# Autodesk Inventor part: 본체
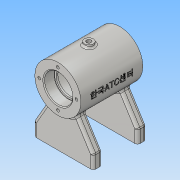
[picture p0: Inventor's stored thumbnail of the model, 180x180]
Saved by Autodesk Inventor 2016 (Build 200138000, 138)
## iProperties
Created: 2018-05
Part Number: 본체
Material: 알루미늄 6061
Document SubType Name: Modeling
Designer: Administrator
Density: 2.7 g/cm^3
Appearance: 알루미늄 - 평지
Mass: 310.015 g
Surface Area: 370.194 cm^2
Volume: 114.821 cm^3
Author: Administrator
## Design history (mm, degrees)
node "작업 평면1"
sketch "스케치1"
  geometry: L1 (32.371, 0)-(-37.629, 0) reference; L2 (32.371, 0)-(-35, 0) reference; L3 (-35, 0)-(-35, 15); L4 (-35, 15)-(32.371, 15); L5 (32.371, 15)-(32.371, 0); L6 (32.371, 15)-(3.504, 65); L7 (3.504, 65)-(-3.504, 65); L8 (-3.504, 65)-(-35, 15); L9 (0, 0)-(0, 88.313) reference; 1 further point
  constraints: 18 end point, 5 horizontal, 2 parallel, 2 perpendicular, 1 midpoint, 1 point on line, 1 vertical, 1 other
  dimensions: "d1" = 70 distance of L1.start L1.end; "d2" = 15 distance of L2.end L3.end; "d3" = 30 deg angle of L5 L6; "d5" = 65 distance between parallel lines of L7 L1
extrude "돌출1" new body sketch "스케치1" distance "d6" = 10; taper "d7" = 0 deg
sketch "스케치2"
  geometry: L1 (0, 0)-(0, 93.301); L2 (-35, 0)-(32.371, 0) reference; C1 r 26 at (0, 65)
  constraints: 2 end point, 1 centre point, 1 point on line, 1 vertical
  dimensions: "d8" = 52 diameter of C1; "d9" = 65 distance from line of L2 C1.centre
extrude "돌출2" join sketch "스케치2" stored distance "d10" = 70; taper "d11" = 0 deg
sketch "스케치3"
  geometry: L1 (20, 44.154)-(30, 44.154) reference; L2 (20, 44.724)-(20, 44.154) reference; L3 (30, 44.724)-(20, 44.724) reference; L4 (30, 44.154)-(30, 44.724) reference; L5 (-30, 44.154)-(-20, 44.154) reference; L6 (-30, 44.724)-(-30, 44.154) reference; L7 (-20, 44.724)-(-30, 44.724) reference; L8 (-20, 44.154)-(-20, 44.724) reference; L9 (-35, 91)-(-35, 39) reference; L10 (35, 39)-(35, 91) reference; L11 (-30, 15)-(-30, 44.154) reference; L12 (-30, 44.154)-(-20, 44.154) reference; L13 (-20, 15)-(-20, 44.154) reference; L14 (-20, 15)-(-30, 15) reference; L15 (-30, 15)-(-30, 44.154) reference; L16 (-20, 0)-(-20, 15) reference; L17 (-30, 0)-(-30, 15) reference; L18 (-20, 0)-(-20, 15) reference; L19 (-20, 0)-(-30, 0) reference; L20 (-30, 0)-(-30, 15) reference; L21 (-20, 15)-(-30, 15) reference; L22 (20, 0)-(20, 15) reference; L23 (20, 15)-(30, 15) reference; L24 (30, 0)-(30, 15) reference; L25 (20, 0)-(30, 0) reference; L26 (20, 44.154)-(30, 44.154) reference; L27 (30, 15)-(30, 44.154) reference; L28 (20, 15)-(30, 15) reference; L29 (20, 15)-(20, 44.154) reference; L30 (0, 0)-(0, 91); L31 (-35, 91)-(35, 91) reference; L32 (-35, 91)-(-35, 39) reference; L33 (-35, 65)-(35, 65); L34 (-35, 65)-(-35, 81); L35 (-35, 81)-(-23.3, 81); L36 (-23, 80.7)-(-23, 79); L37 (-23, 79)-(-21, 79); L38 (-21, 79)-(-21, 83); L39 (-18, 86)-(18, 86); L40 (21, 83)-(21, 79); L41 (21, 79)-(23, 79); L42 (23, 79)-(23, 80.7); L43 (23.3, 81)-(35, 81); L44 (35, 39)-(35, 91) reference; L45 (35, 81)-(35, 65); A1 r 0.3 centre (-23.3, 80.7) between (-23, 80.7) and (-23.3, 81); A2 r 0.3 centre (23.3, 80.7) between (23.3, 81) and (23, 80.7); A3 r 3 centre (-18, 83) between (-18, 86) and (-21, 83); A4 r 3 centre (18, 83) between (21, 83) and (18, 86); 2 further points
  constraints: 26 end point, 9 point on line, 8 point on circle, 8 tangent, 6 perpendicular, 4 centre point, 3 midpoint, 2 equal radius, 2 horizontal, 1 collinear
  dimensions: "d12" = 12 distance of L34.end point (-23, 81); "d13" = 12 distance of point (23, 81) L43.end; "d14" = 2 distance of L36.end L37.end; "d15" = 2 distance of L40.end L41.end; "d16" = 32 diameter of L35 L33; "d17" = 28 diameter of L37 L33; "d18" = 42 diameter of L39 L33; "d19" = 0.3 radius of A1; "d20" = 3 radius of A3
revolve "회전1" sketch "스케치3" stored, may be unused: angle "d21" = 90 deg
chamfer "모따기1" distance "d22" = 1; stored, may be unused: second distance "d23" = 2, angle "d24" = 45 deg
chamfer "모따기2" distance "d25" = 1; stored, may be unused: second distance "d26" = 2, angle "d27" = 45 deg
node "작업 평면3"
  node "작업 평면2"
sketch "스케치4"
  geometry: L1 (-26, -35)-(26, -35) reference; L2 (26, 35)-(-26, 35) reference; L3 (0, 0)-(0, 35); C1 r 5 at (0, 0); 1 further point
  constraints: 2 coincident, 2 end point, 1 centre point, 1 midpoint
  dimensions: "d29" = 10 diameter of C1
extrude "돌출3" join sketch "스케치4" stored distance "d30" = 70; taper "d31" = 0 deg
hole "구멍1" diameter "d34" = 5.188; stored, may be unused: countersink angle "d38" = 90 deg, drill point angle "d40" = 118 deg; dims "d35" = 12, "d36" = 4, "d37" = 2, "d39" = 16, "d41" = 10, "d42" = 10
node "작업 평면5"
  node "작업 평면4"
sketch "스케치5"
  geometry: L1 (-35, 26)-(35, 26) reference; L2 (-35, 26)-(-35, -26) reference; 2 further points
  constraints: 1 other
  dimensions: "d44" = 26 distance from line of L1 point (0, 0); "d45" = 35 distance from line of L2 point (0, 0)
feature "엠보싱1" sketch "스케치5" dims "d46" = 0.5, "d47" = 0
sketch "스케치6"
  geometry: L1 (61, -15)-(61, 55) reference; L2 (61, 20)-(-10.533, 20); L3 (61, 55)-(9, 55) reference; L4 (35, 55)-(35, -15); L5 (9, -15)-(61, -15) reference; L6 (67.371, 40)-(67.371, 50) reference; L7 (67.371, 45)-(0, 45); L8 (0, 40)-(0, 50) reference; 3 further points
  constraints: 6 end point, 5 midpoint, 1 horizontal, 1 point on line, 1 symmetric about line
  dimensions: "d50" = 20 distance from line of point (55, 45) L4
hole "구멍2" sketch "스케치6" at (55, 45), (15, 45) diameter "d51" = 4.134; stored, may be unused: countersink angle "d55" = 90 deg, drill point angle "d57" = 118 deg; dims "d52" = 8, "d53" = 4, "d54" = 2, "d56" = 10
sketch "스케치7" dims "d58" = 42
  geometry: 4 further points
  constraints: 5 other
hole "구멍3" sketch "스케치7" at (-0.11, 21) diameter "d59" = 3.242; stored, may be unused: countersink angle "d63" = 90 deg, drill point angle "d65" = 118 deg; dims "d60" = 8, "d61" = 4, "d62" = 2, "d64" = 10
sketch "스케치8"
  geometry: L1 (0, 65)-(-46.973, 65.589) reference; L2 (0, 98.841)-(0, 0) reference; L3 (0, 65)-(8.893, 40.568); C1 r 17 at (0, 65) reference; 2 further points
  constraints: 6 end point, 2 vertical, 1 coincident, 5 other
  dimensions: "d87" = 20 deg angle of L3 L2
fillet "모깎기2" dims "d84" = 2
fillet "모깎기3" dims "d85" = 3
fillet "모깎기4" dims "d86" = 3
node "작업 평면9"
  node "작업 평면8"
sketch "스케치10"
  geometry: C1 r 6 at (0, 0); 1 further point
  constraints: 1 centre point
  dimensions: "d89" = 12 diameter of C1
extrude "돌출5" join sketch "스케치10" stored distance "d90" = 70; taper "d91" = 0 deg
hole "구멍5" diameter "d94" = 5.188; stored, may be unused: countersink angle "d98" = 90 deg, drill point angle "d100" = 118 deg; dims "d92" = 10, "d93" = 10, "d95" = 12, "d96" = 4, "d97" = 2, "d99" = 16
fillet "모깎기5" dims "d101" = 2
node "솔리드1"
mirror "대칭1"
mirror "대칭2"
pattern_circular "원형 패턴1" dims angle "d67" = 360 deg
mirror "대칭3"
node "투영된 루프1"
node "투영된 루프2"
node "투영된 루프3"
node "투영된 루프4"
node "투영된 루프5"
other parameters: "d28" = 3, "d43" = 0.5, "d88" = 3
